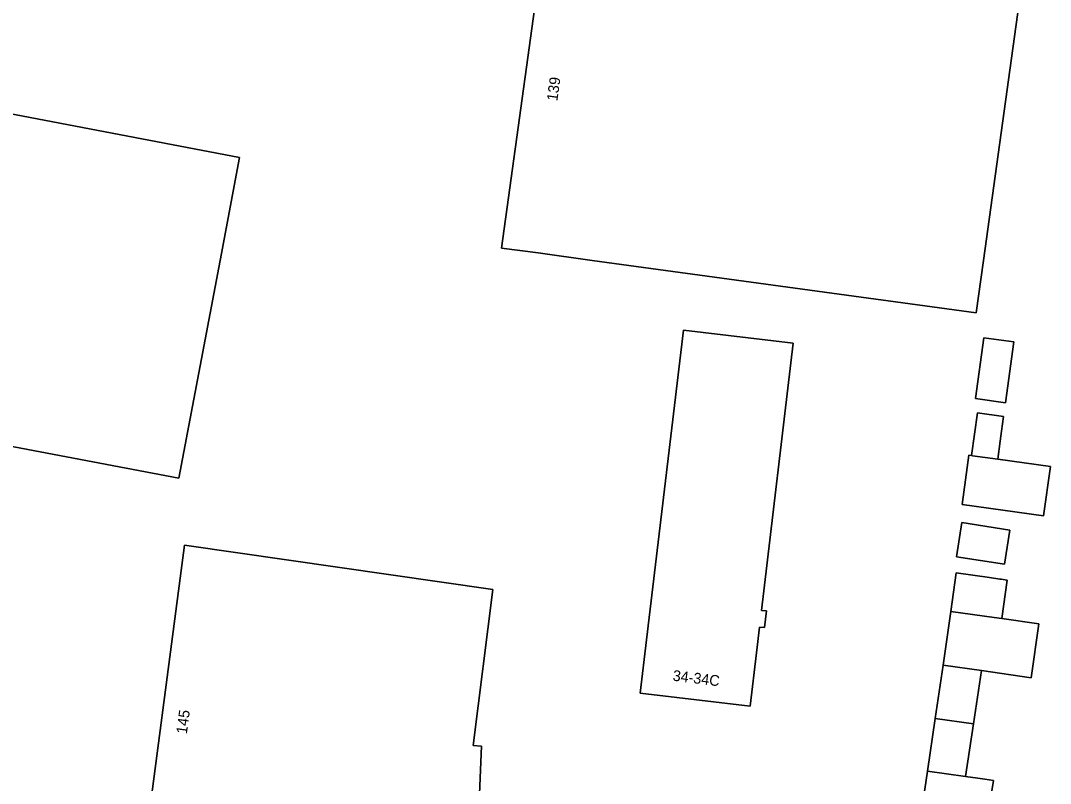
# Model space of a CAD drawing. Extents: x 161692 to 162379, y 380760 to 381678.
# Drawn here: x 161868.2 to 161964.1, y 381451.3 to 381522.3 of the extents above; entities that cross this region are included whole.
import ezdxf

# ---------------------------------------------------------------- set-up
doc = ezdxf.new("R2010")
doc.units = 0
for name, color, linetype in [('IMGEO_Erf', 7, 'Continuous'), ('IMGEO_Pand', 7, 'Continuous'), ('IMGEO_Pand_nummerreeks', 7, 'Continuous')]:
    doc.layers.add(name, color=color, linetype=linetype)

msp = doc.modelspace()

# ---------------------------------------------------------------- linework, layer by layer
at = {"layer": 'IMGEO_Erf'}
for points in [[(161921.448, 381500), (161916.423, 381500.686), (161913.027, 381501.149), (161917.268, 381531.951), (161961.487, 381525.822), (161957.904, 381500), (161957.227, 381495.118)], [(161846.666, 381486.611), (161844.658, 381486.992), (161839.756, 381487.911), (161840.226, 381490.398), (161844.962, 381515.465), (161845.408, 381517.824), (161850.308, 381516.878), (161852.381, 381516.483), (161888.637, 381509.574), (161886.826, 381500), (161882.989, 381479.719)], [(161929.968, 381493.506), (161940.182, 381492.301), (161937.216, 381467.414), (161937.685, 381467.358), (161937.499, 381465.803), (161937.041, 381465.857), (161936.755, 381463.455), (161936.163, 381458.49), (161925.942, 381459.709), (161926.534, 381464.674)], [(161957.922, 381492.801), (161960.719, 381492.422), (161959.949, 381486.746), (161957.154, 381487.135)], [(161957.332, 381485.793), (161959.774, 381485.453), (161959.589, 381484.089), (161959.465, 381483.175), (161959.235, 381481.481), (161964.133, 381480.799), (161963.496, 381476.226), (161955.911, 381477.282), (161956.547, 381481.855), (161956.779, 381481.823)], [(161955.879, 381475.581), (161960.345, 381474.881), (161959.847, 381471.699), (161955.38, 381472.398)]]:
    msp.add_lwpolyline(points, close=True, dxfattribs=at)
for points in [[(161879.319, 381441.58), (161883.512, 381473.475), (161912.215, 381469.344), (161910.39, 381454.832), (161911.149, 381454.764), (161910.891, 381448.108)], [(161951.949, 381447.414), (161952.687, 381452.45), (161953.403, 381457.334), (161954.134, 381462.32), (161954.851, 381467.31), (161955.367, 381470.907), (161958.472, 381470.462), (161959.424, 381470.325), (161959.555, 381470.306), (161960.115, 381470.226), (161959.601, 381466.647), (161963.054, 381466.151), (161962.334, 381461.142), (161957.727, 381461.804), (161956.977, 381456.836), (161956.24, 381451.955), (161957.389, 381451.782), (161958.024, 381451.686), (161958.83, 381451.565), (161958.63, 381450.243)]]:
    msp.add_lwpolyline(points, dxfattribs=at)
at = {"layer": 'IMGEO_Pand'}
for points in [[(161957.904, 381500), (161961.487, 381525.822), (161917.268, 381531.951), (161913.027, 381501.149), (161916.423, 381500.686), (161921.448, 381500), (161957.227, 381495.118)], [(161882.989, 381479.719), (161886.826, 381500), (161888.637, 381509.574), (161852.381, 381516.483), (161850.308, 381516.878), (161845.408, 381517.824), (161844.962, 381515.465), (161840.226, 381490.398), (161839.756, 381487.911), (161844.658, 381486.992), (161846.666, 381486.611)], [(161940.182, 381492.301), (161929.968, 381493.506), (161926.534, 381464.674), (161925.942, 381459.709), (161936.163, 381458.49), (161936.755, 381463.455), (161937.041, 381465.857), (161937.499, 381465.803), (161937.685, 381467.358), (161937.216, 381467.414)], [(161957.154, 381487.135), (161959.949, 381486.746), (161960.719, 381492.422), (161957.922, 381492.801)], [(161956.779, 381481.823), (161956.878, 381481.809), (161959.235, 381481.481), (161959.465, 381483.175), (161959.589, 381484.089), (161959.774, 381485.453), (161957.332, 381485.793)], [(161964.133, 381480.799), (161959.235, 381481.481), (161956.878, 381481.809), (161956.779, 381481.823), (161956.547, 381481.855), (161955.911, 381477.282), (161963.496, 381476.226)], [(161955.38, 381472.398), (161959.847, 381471.699), (161960.345, 381474.881), (161955.879, 381475.581)], [(161911.149, 381454.764), (161910.39, 381454.832), (161912.215, 381469.344), (161883.512, 381473.475), (161879.319, 381441.58), (161879.258, 381441.115), (161910.592, 381440.354), (161910.597, 381440.505), (161910.891, 381448.108)], [(161958.472, 381470.462), (161955.367, 381470.907), (161954.851, 381467.31), (161958.91, 381466.746), (161959.601, 381466.647), (161960.115, 381470.226), (161959.555, 381470.306), (161959.424, 381470.325)], [(161963.054, 381466.151), (161959.601, 381466.647), (161958.91, 381466.746), (161954.851, 381467.31), (161954.134, 381462.32), (161957.727, 381461.804), (161962.334, 381461.142)], [(161957.727, 381461.804), (161954.134, 381462.32), (161953.403, 381457.334), (161956.977, 381456.836)], [(161953.403, 381457.334), (161952.687, 381452.45), (161956.24, 381451.955), (161956.977, 381456.836)], [(161957.389, 381451.782), (161956.24, 381451.955), (161952.687, 381452.45), (161951.949, 381447.414), (161956.517, 381446.795), (161958.074, 381446.56), (161958.366, 381448.495), (161958.63, 381450.243), (161958.83, 381451.565), (161958.024, 381451.686)]]:
    msp.add_lwpolyline(points, close=True, dxfattribs=at)

# ---------------------------------------------------------------- texts
at = {"layer": 'IMGEO_Pand_nummerreeks'}
for s, rotation, p in [('139', 82.16044, (161918.216, 381514.787)), ('34-34C', 352.99846, (161928.921, 381460.874)), ('145', 82.51165, (161883.719, 381455.866))]:
    msp.add_text(s, height=1, rotation=rotation, dxfattribs=at).set_placement(p)

doc.saveas('drawing.dxf')
